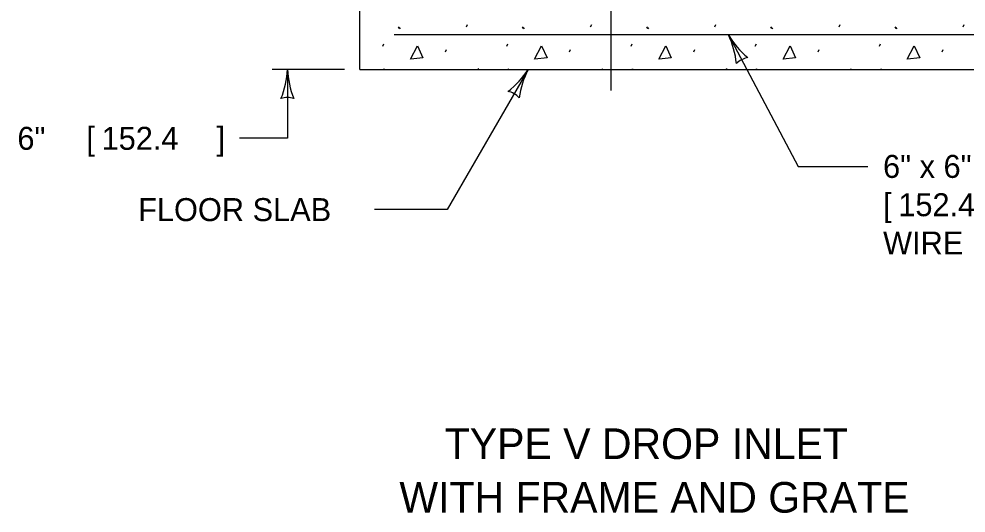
# Model space of a CAD drawing. Extents: x 49991.4 to 50041.6, y 49987.6 to 50011.4.
# Drawn here: x 50025.104 to 50027.575, y 49989.989 to 49991.279 of the extents above; entities that cross this region are included whole.
import ezdxf

# ---------------------------------------------------------------- set-up
doc = ezdxf.new("R2010")
doc.units = 0
for name, color, linetype in [('Level 1', 7, 'Continuous'), ('Level 2', 7, 'Continuous'), ('Level 3', 7, 'Continuous')]:
    doc.layers.add(name, color=color, linetype=linetype)

msp = doc.modelspace()

# ---------------------------------------------------------------- linework, layer by layer
at = {"layer": 'Level 1'}
for p, q in [((50026.2714, 49991.258), (50026.2741, 49991.2641)), ((50026.5956, 49991.258), (50026.5983, 49991.2641)), ((50026.9197, 49991.258), (50026.9224, 49991.2641)), ((50027.2438, 49991.258), (50027.2465, 49991.2641)), ((50027.568, 49991.258), (50027.5707, 49991.2641)), ((50027.6387, 49991.2369), (50026.0832, 49991.2369)), ((50026.0928, 49991.258), (50026.0955, 49991.2539)), ((50026.0955, 49991.2564), (50026.0982, 49991.2524)), ((50026.4169, 49991.258), (50026.4196, 49991.2539)), ((50026.4196, 49991.2564), (50026.4223, 49991.2524)), ((50026.741, 49991.258), (50026.7437, 49991.2539)), ((50026.7437, 49991.2564), (50026.7465, 49991.2524)), ((50027.0652, 49991.258), (50027.0679, 49991.2539)), ((50027.0679, 49991.2564), (50027.0706, 49991.2524)), ((50027.3893, 49991.258), (50027.392, 49991.2539)), ((50027.392, 49991.2564), (50027.3947, 49991.2524)), ((50026.0528, 49991.2078), (50026.0555, 49991.2139)), ((50026.377, 49991.2078), (50026.3797, 49991.2139)), ((50026.7011, 49991.2078), (50026.7038, 49991.2139)), ((50027.0252, 49991.2078), (50027.028, 49991.2139)), ((50027.3494, 49991.2078), (50027.3521, 49991.2139)), ((50026.2166, 49991.1923), (50026.2193, 49991.1984)), ((50026.5407, 49991.1923), (50026.5434, 49991.1984)), ((50026.8649, 49991.1923), (50026.8676, 49991.1984)), ((50027.189, 49991.1923), (50027.1917, 49991.1984)), ((50027.5132, 49991.1923), (50027.5159, 49991.1984)), ((50025.9932, 49991.1469), (50027.7287, 49991.1469)), ((50026.3012, 49991.149), (50026.3025, 49991.1469)), ((50026.6253, 49991.149), (50026.6267, 49991.1469)), ((50026.9495, 49991.149), (50026.9508, 49991.1469)), ((50027.2736, 49991.149), (50027.2749, 49991.1469))]:
    msp.add_line(p, q, dxfattribs=at)
for points in [[(50025.9932, 49991.1469), (50025.9932, 49991.3269), (50027.7287, 49991.3269), (50027.7287, 49991.1469)], [(50026.1253, 49991.174), (50026.1435, 49991.2085), (50026.1577, 49991.1767), (50026.1259, 49991.174)], [(50026.4494, 49991.174), (50026.4677, 49991.2085), (50026.4819, 49991.1767), (50026.4501, 49991.174)], [(50026.7735, 49991.174), (50026.7918, 49991.2085), (50026.806, 49991.1767), (50026.7742, 49991.174)], [(50027.0977, 49991.174), (50027.1159, 49991.2085), (50027.1301, 49991.1767), (50027.0983, 49991.174)], [(50027.4218, 49991.174), (50027.4401, 49991.2085), (50027.4543, 49991.1767), (50027.4225, 49991.174)], [(50026.0556, 49991.1469), (50026.0562, 49991.1483), (50026.058, 49991.1469)], [(50026.3797, 49991.1469), (50026.3804, 49991.1483), (50026.3821, 49991.1469)], [(50026.7039, 49991.1469), (50026.7045, 49991.1483), (50026.7063, 49991.1469)], [(50027.028, 49991.1469), (50027.0286, 49991.1483), (50027.0304, 49991.1469)], [(50027.3521, 49991.1469), (50027.3528, 49991.1483), (50027.3545, 49991.1469)]]:
    msp.add_lwpolyline(points, dxfattribs=at)
at = {"layer": 'Level 3'}
for p, q in [((50026.6481, 49991.3703), (50026.6481, 49991.0914)), ((50026.9552, 49991.2369), (50027.1367, 49990.8936)), ((50025.9532, 49991.1469), (50025.7642, 49991.1469)), ((50025.8042, 49991.1469), (50025.8042, 49990.9669)), ((50026.4325, 49991.1469), (50026.2209, 49990.7808)), ((50025.8042, 49990.9669), (50025.679, 49990.9669)), ((50027.1367, 49990.8936), (50027.3187, 49990.8936)), ((50026.2209, 49990.7808), (50026.0319, 49990.7808))]:
    msp.add_line(p, q, dxfattribs=at)
for centre, radius, start, end in [((50026.7545, 49991.1412), 0.2223, 5.3258, 25.5093), ((50027.1555, 49991.3559), 0.233, 210.6971, 229.9469), ((50026.7545, 49991.1412), 0.2223, 5.3258, 25.5093), ((50027.1555, 49991.3559), 0.233, 210.6971, 229.9469), ((50027.0151, 49991.1236), 0.0548, 100.0086, 135.731), ((50027.0151, 49991.1236), 0.0548, 100.0086, 135.731), ((50025.5821, 49991.1561), 0.2223, 337.456, 357.6395), ((50026.0369, 49991.1584), 0.233, 182.8273, 202.0772), ((50026.2448, 49991.266), 0.2223, 307.4275, 327.611), ((50026.2448, 49991.266), 0.2223, 307.4275, 327.611), ((50026.6397, 49991.0404), 0.233, 152.7988, 172.0486), ((50026.6397, 49991.0404), 0.233, 152.7988, 172.0486), ((50026.3683, 49991.0359), 0.0548, 42.1103, 77.8326), ((50026.3683, 49991.0359), 0.0548, 42.1103, 77.8326), ((50025.8042, 49991.0187), 0.0548, 72.1388, 107.8612)]:
    msp.add_arc(centre, radius, start, end, dxfattribs=at)

# ---------------------------------------------------------------- texts
at = {"layer": 'Level 2'}
for s, p in [('6" ', (50025.0995, 49990.9369)), ('[', (50025.2795, 49990.9369)), ('152.4', (50025.3192, 49990.9369)), (']', (50025.6192, 49990.9369)), ('6" x 6" x W2.9', (50027.3587, 49990.8636)), ('[', (50027.3587, 49990.7636)), ('152.4 x 152.4 x MW 18.71', (50027.3984, 49990.7636)), ('FLOOR SLAB', (50025.4146, 49990.7508)), ('WIRE MESH', (50027.3587, 49990.6636))]:
    msp.add_text(s, height=0.06, rotation=360, dxfattribs=at).set_placement(p)
for s, p in [('TYPE V DROP INLET', (50026.2148, 49990.1296)), ('WITH FRAME AND GRATE', (50026.0964, 49989.9896))]:
    msp.add_text(s, height=0.08, dxfattribs=at).set_placement(p)

doc.saveas('drawing.dxf')
